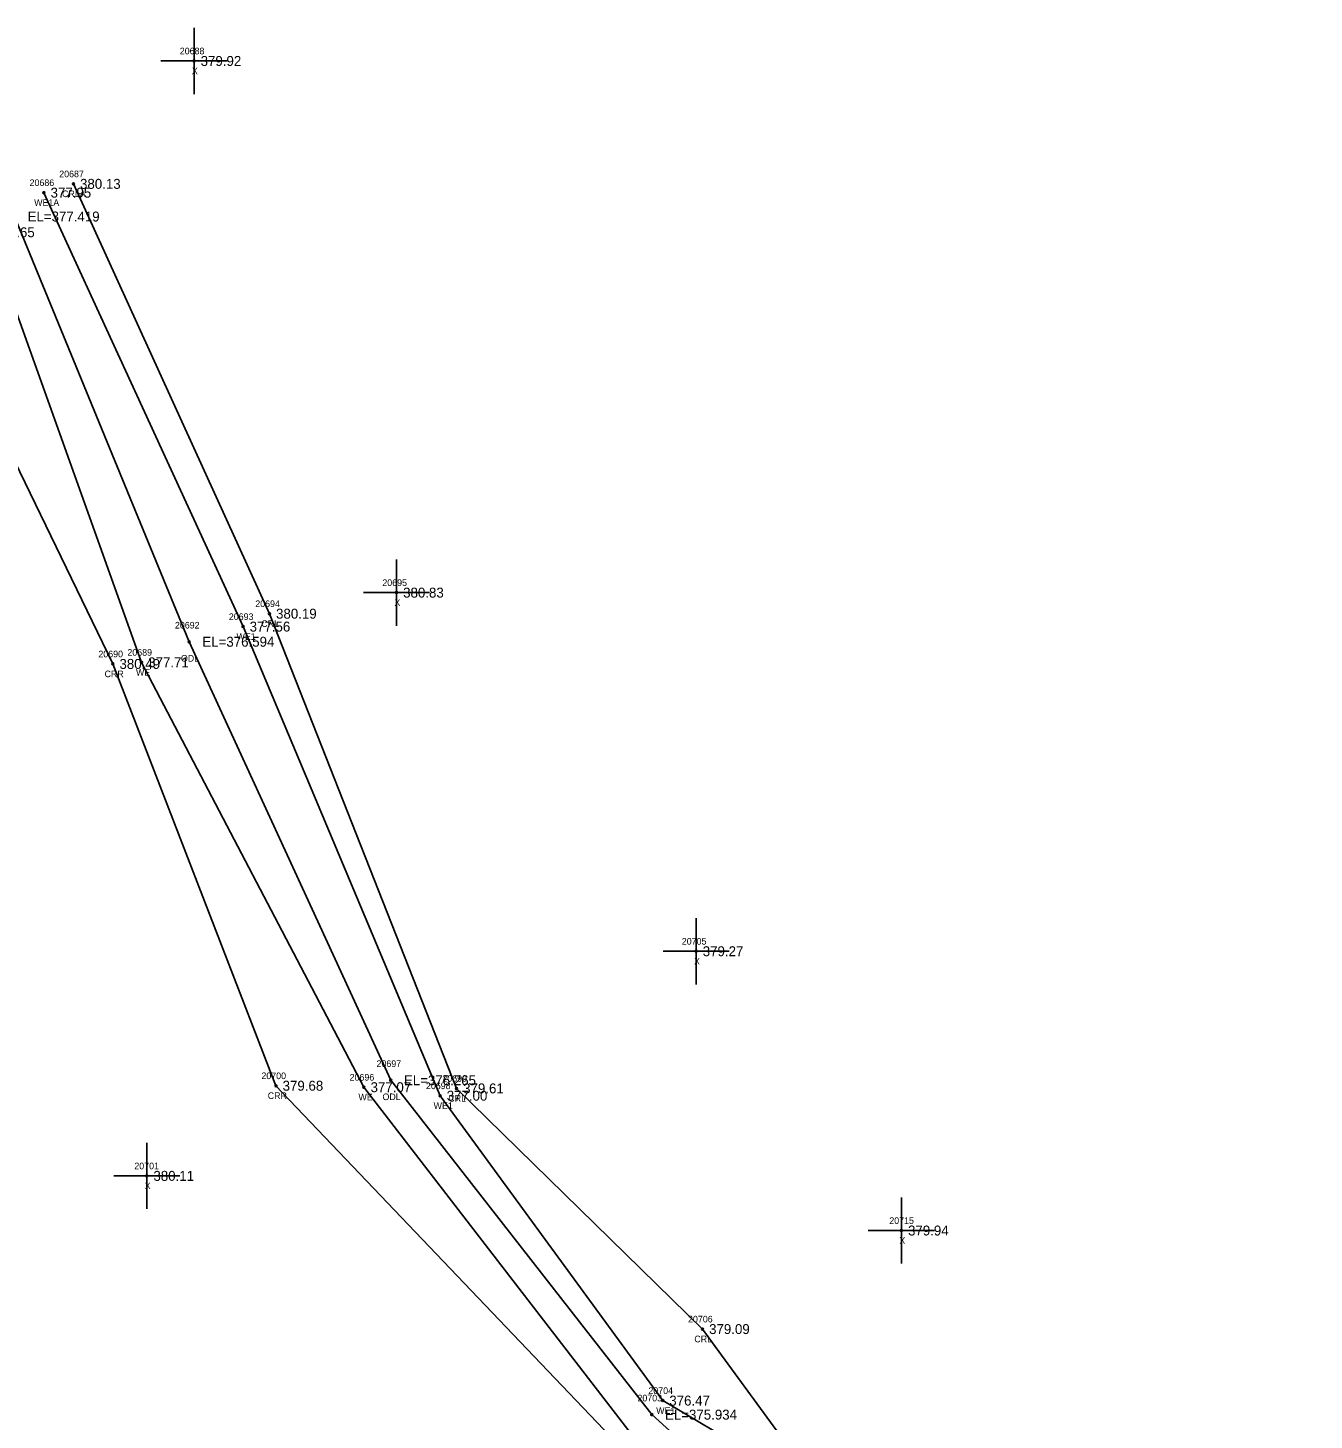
# Model space of a CAD drawing. Extents: x 2116373 to 2118139, y 979529 to 981026.
# Drawn here: x 2117048.4 to 2117242.6, y 980346.7 to 980557 of the extents above; entities that cross this region are included whole.
import ezdxf

# ---------------------------------------------------------------- set-up
doc = ezdxf.new("R2010")
doc.units = 0
for name, color, linetype in [('RD_EX_H2O', 7, 'Continuous'), ('RD_EX_H2O_txCode', 7, 'Continuous'), ('RD_EX_Misc', 7, 'Continuous'), ('RD_EX_Misc_txCode', 7, 'Continuous'), ('RD_EX_TX_H2O_ELEV', 7, 'Continuous'), ('RD_EX_TX_Misc_ELEV', 7, 'Continuous'), ('RD_SMD_Locator', 7, 'Continuous')]:
    doc.layers.add(name, color=color, linetype=linetype)

msp = doc.modelspace()

# ---------------------------------------------------------------- linework, layer by layer
at = {"layer": 'RD_EX_H2O'}
for points in [[(2117055.27, 980533.4), (2117084.87, 980468.5), (2117113.12, 980396.82), (2117150.26, 980360.48), (2117172.14, 980330.53), (2117167.4, 980300.56), (2117152, 980282.05), (2117153.33, 980268.31), (2117164.01, 980260.72), (2117221.6, 980247.26), (2117265.25, 980211.02), (2117324.27, 980199.15), (2117347.37, 980175.31), (2117365.85, 980182.55), (2117389.45, 980162.29), (2117399.63, 980142.01), (2117411.26, 980120.88), (2117420.42, 980068.64), (2117446.24, 980057.21), (2117497.11, 980045.39), (2117594.71, 979999.33), (2117646.33, 979985.56), (2117750.91, 980032.44), (2117805.09, 980018.87)], [(2117050.82, 980532.07), (2117080.88, 980466.55), (2117110.64, 980395.71), (2117144.25, 980349.68), (2117164.75, 980337.49), (2117167.1, 980320.28), (2117162.85, 980307.87), (2117148.28, 980284.4), (2117152.02, 980266.59), (2117158.19, 980257.22), (2117219.84, 980245.38), (2117260.42, 980200.03), (2117320.83, 980195.76), (2117348.44, 980166.4)], [(2117046.35, 980528.47), (2117072.74, 980464.26), (2117103.18, 980398.05), (2117142.6, 980347.56), (2117158.28, 980333.4), (2117157.84, 980320.26), (2117155.72, 980311.74), (2117145.74, 980285.73), (2117146.15, 980263.73), (2117154.31, 980252.06), (2117214.06, 980237.52), (2117257.08, 980196.51), (2117314.34, 980190.71), (2117327.56, 980176.76), (2117343.89, 980156.23)], [(2117042.29, 980526.09), (2117065.56, 980461.15), (2117099.14, 980397), (2117139.48, 980344.65), (2117153.05, 980329.52), (2117152.49, 980324.98), (2117153.14, 980319.82), (2117152.6, 980312.45), (2117140.5, 980286.71), (2117130.05, 980269.91), (2117147.41, 980248.1), (2117202.36, 980228.49), (2117250.8, 980193.52), (2117312.93, 980184.75), (2117333.66, 980167.27), (2117332.31, 980165.61), (2117330.39, 980165.66), (2117305.03, 980166.54), (2117306.15, 980158.45), (2117334.27, 980149.08), (2117359.88, 980134.92)], [(2117031.59, 980522.05), (2117061.22, 980460.91), (2117085.86, 980397.22), (2117136.43, 980344.22), (2117150.07, 980329.14), (2117146.87, 980313.29), (2117136.68, 980286.81), (2117127.11, 980271.21), (2117134.99, 980253.7), (2117146.93, 980245.3), (2117201.17, 980227.79), (2117241.16, 980199.52)]]:
    msp.add_lwpolyline(points, dxfattribs=at)
at = {"layer": 'RD_EX_Misc'}
for p, q in [((2117073.48, 980546.96), (2117073.48, 980556.96)), ((2117068.48, 980551.96), (2117078.48, 980551.96)), ((2117104.06, 980466.68), (2117104.06, 980476.68)), ((2117099.06, 980471.68), (2117109.06, 980471.68)), ((2117149.3, 980412.53), (2117149.3, 980422.53)), ((2117144.3, 980417.53), (2117154.3, 980417.53)), ((2117066.35, 980378.61), (2117066.35, 980388.61)), ((2117061.35, 980383.61), (2117071.35, 980383.61)), ((2117180.3, 980370.36), (2117180.3, 980380.36)), ((2117175.3, 980375.36), (2117185.3, 980375.36))]:
    msp.add_line(p, q, dxfattribs=at)
at = {"layer": 'RD_SMD_Locator'}
for centre in [(2117073.48, 980551.96), (2117055.27, 980533.4), (2117050.82, 980532.07), (2117104.06, 980471.68), (2117084.87, 980468.5), (2117080.88, 980466.55), (2117072.74, 980464.26), (2117061.22, 980460.91), (2117065.56, 980461.15), (2117149.3, 980417.53), (2117103.18, 980398.05), (2117085.86, 980397.22), (2117099.14, 980397), (2117113.12, 980396.82), (2117110.64, 980395.71), (2117066.35, 980383.61), (2117180.3, 980375.36), (2117150.26, 980360.48), (2117144.25, 980349.68), (2117142.6, 980347.56)]:
    msp.add_circle(centre, 0.15, dxfattribs=at)

# ---------------------------------------------------------------- texts
at = {"layer": 'RD_EX_H2O_txCode'}
for s, p in [('20687', (2117053.13, 980534.4)), ('20686', (2117048.65, 980533.07)), ('WE1A', (2117049.34, 980530.07)), ('CRLA', (2117053.55, 980531.4)), ('20694', (2117082.73, 980469.5)), ('20693', (2117078.74, 980467.55)), ('CRL', (2117083.64, 980466.5)), ('20692', (2117070.6, 980466.26)), ('WE1', (2117079.9, 980464.55)), ('20689', (2117063.42, 980462.15)), ('20690', (2117059.04, 980461.91)), ('ODL', (2117071.5, 980461.26)), ('CRR', (2117059.97, 980458.91)), ('WE', (2117064.72, 980459.15)), ('20697', (2117101.04, 980400.05)), ('20700', (2117083.66, 980398.22)), ('20696', (2117096.98, 980398)), ('20699', (2117110.98, 980397.82)), ('CRR', (2117084.61, 980395.22)), ('WE', (2117098.31, 980395)), ('ODL', (2117101.94, 980395.05)), ('20698', (2117108.5, 980396.71)), ('WE1', (2117109.66, 980393.71)), ('CRL', (2117111.89, 980394.82)), ('20706', (2117148.08, 980361.48)), ('CRL', (2117149.03, 980358.48)), ('20703', (2117140.44, 980349.56)), ('20704', (2117142.09, 980350.68)), ('WE1', (2117143.27, 980347.68))]:
    msp.add_text(s, height=1, dxfattribs=at).set_placement(p)
at = {"layer": 'RD_EX_Misc_txCode'}
for s, p in [('20688', (2117071.33, 980552.96)), ('X', (2117073.16, 980549.96)), ('20695', (2117101.92, 980472.68)), ('X', (2117103.74, 980469.68)), ('20705', (2117147.14, 980418.53)), ('X', (2117148.99, 980415.53)), ('20701', (2117064.47, 980384.61)), ('X', (2117066.03, 980381.61)), ('20715', (2117178.47, 980376.36)), ('X', (2117179.99, 980373.36))]:
    msp.add_text(s, height=1, dxfattribs=at).set_placement(p)
at = {"layer": 'RD_EX_TX_H2O_ELEV'}
for s, p in [('377.95', (2117051.82, 980531.32)), ('380.13', (2117056.27, 980532.65)), ('EL=377.419', (2117048.35, 980527.72)), ('377.65', (2117043.29, 980525.34)), ('380.19', (2117085.87, 980467.75)), ('377.56', (2117081.88, 980465.8)), ('EL=376.594', (2117074.74, 980463.51)), ('380.49', (2117062.22, 980460.16)), ('377.71', (2117066.56, 980460.4)), ('379.68', (2117086.86, 980396.47)), ('EL=376.265', (2117105.18, 980397.3)), ('377.07', (2117100.14, 980396.25)), ('377.00', (2117111.64, 980394.96)), ('379.61', (2117114.12, 980396.07)), ('379.09', (2117151.26, 980359.73)), ('376.47', (2117145.25, 980348.93)), ('EL=375.934', (2117144.6, 980346.81))]:
    msp.add_text(s, height=1.5, dxfattribs=at).set_placement(p)
at = {"layer": 'RD_EX_TX_Misc_ELEV'}
for s, p in [('379.92', (2117074.48, 980551.21)), ('380.83', (2117105.06, 980470.93)), ('379.27', (2117150.3, 980416.78)), ('380.11', (2117067.35, 980382.86)), ('379.94', (2117181.3, 980374.61))]:
    msp.add_text(s, height=1.5, dxfattribs=at).set_placement(p)

doc.saveas('drawing.dxf')
